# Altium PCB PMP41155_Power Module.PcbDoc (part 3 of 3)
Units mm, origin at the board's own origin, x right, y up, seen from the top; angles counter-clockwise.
Board outline 40.5 x 74.05 mm, 8 copper layers (Top Layer, Layer 1, Layer 2, Layer 3, Layer 4, Layer 5, Layer 6, Bottom Layer), stack 1.58 mm thick; 130 components, 51 nets, 407 pads, 560 vias.
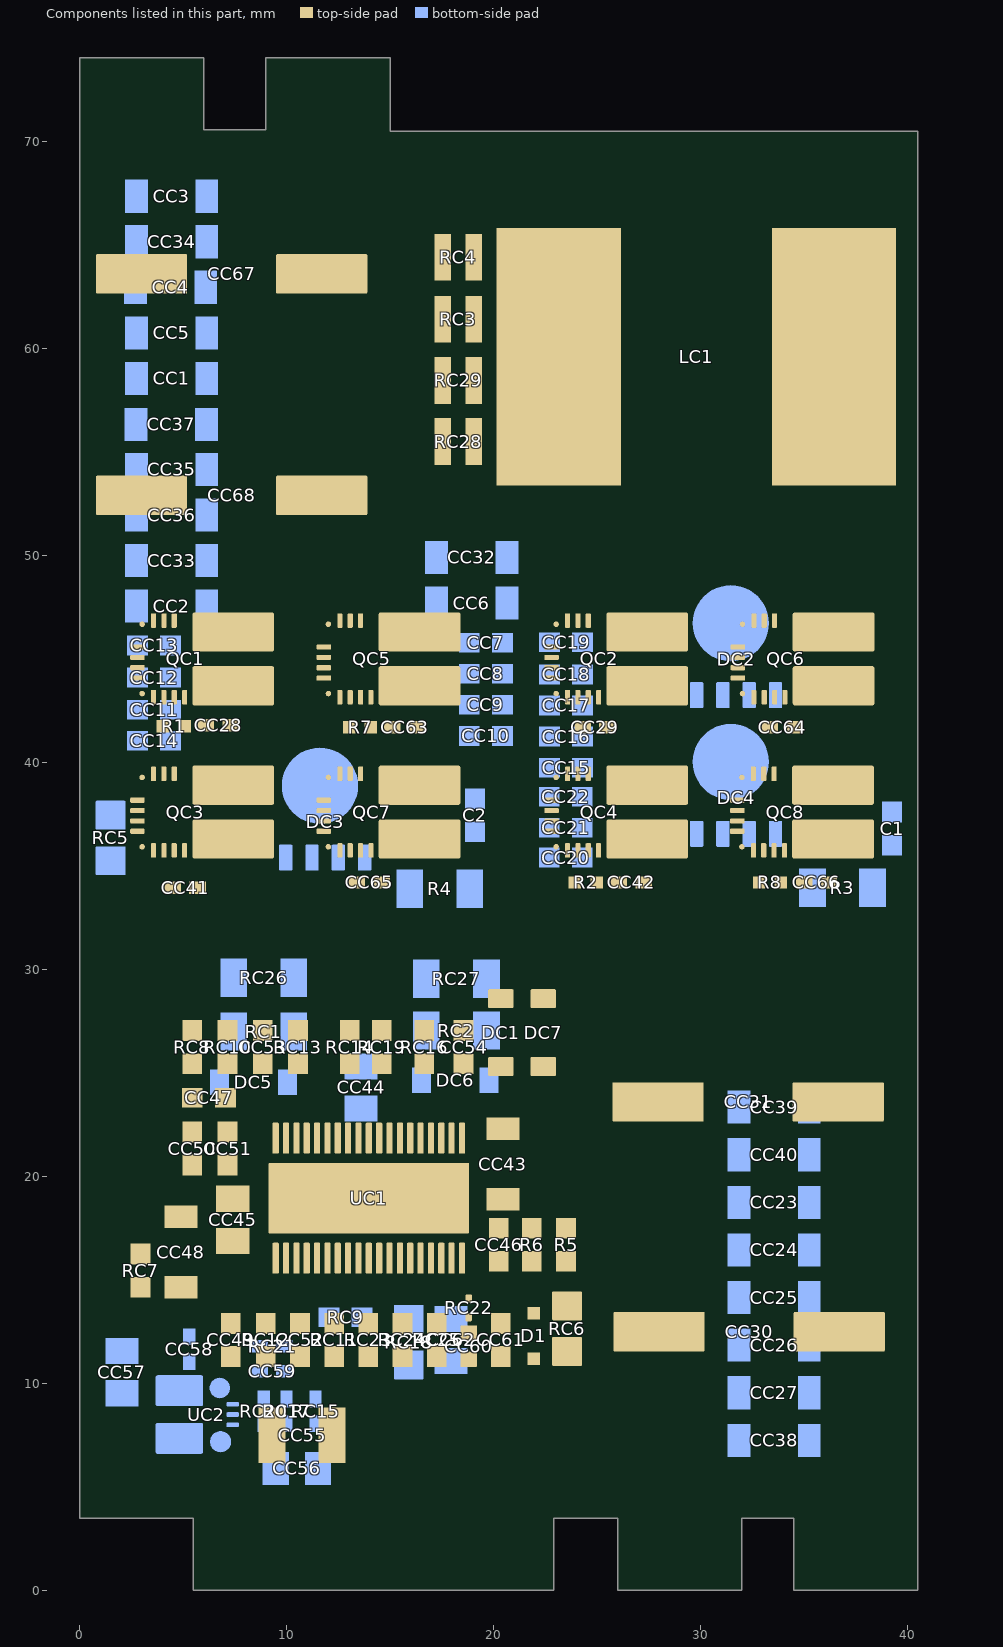
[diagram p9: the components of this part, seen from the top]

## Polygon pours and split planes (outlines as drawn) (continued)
VBUS1 on Bottom Layer "BOTTOM_LAYER_VBUS1_P263" (solid, pour order 263): 31.3,2.6 31.3,3.25 33.8,5.75 33.8,24.05 33,24.85 24.5,24.85 21.9,22.25 21.9,5.75 25.05,2.6
SGND on Bottom Layer "BOTTOM_LAYER_SGND_P221" (solid, remove dead copper, pour order 221): 0.474,5.644 2.624,3.494 19.524,3.494 20.352,4.321 20.352,22.116 19.975,22.494 1.344,22.494 0.474,21.624
SW2 on Bottom Layer "BOTTOM_LAYER_SW2_P250" (solid, pour order 250): 27.45,70 39.55,70 40,69.55 40,43.5 39.3,42.8 20.45,42.8 20,43.25 20,50.45 22.05,52.5 26.45,52.5 26.95,53 26.95,69.5
CSA_DISCH on Bottom Layer "BOTTOM_LAYER_CSA_DISCH_P144" (solid, pour order 144): 5.25,44.85 6,45.6 17.685,45.6 18.189,45.096 18.189,40.711 18.3,40.6 19.65,40.6 19.65,37.5 19.5,37.35 18,37.35 17.45,37.9 5.45,37.9 5.25,38.1
CSB_DISCH on Bottom Layer "BOTTOM_LAYER_CSB_DISCH_P237" (solid, pour order 237): 18.5,69.65 18.85,70 26.05,70 26.55,69.5 26.55,53.5 26.05,53 19,53 18.5,53.5 18.5,69.6
CSA_DISCH on Bottom Layer "BOTTOM_LAYER_CSA_DISCH_P253" (solid, pour order 253): 15.35,69.5 15.85,70 17.85,70 19.2,68.65 19.2,54.3 17.6,52.7 16.1,52.7 15.35,53.45
SGND on Bottom Layer "BOTTOM_LAYER_SGND_P233" (solid, pour order 233): 4.95,37.4 17.7,37.4 17.95,37.15 17.9,37.1 17.9,33.8 16.9,32.8 4.9,32.8 3.45,34.25 3.45,35.9
NetC2_2 on Bottom Layer "BOTTOM_LAYER_NETC2_2_P232" (solid, pour order 232): 19.7,37.175 19.85,37.025 19.85,32.975 19.75,32.875 18.2,32.875 18.05,33.025 18.05,37.075 18.15,37.175
VBUS1 on Bottom Layer "BOTTOM_LAYER_VBUS1_P231" (solid, pour order 231): 24.25,51.1 39.7,51.1 40.05,50.75 40.05,44.5 39.8,44.25 25.4,44.25 24.9,43.75 24.9,35 24.8,34.9 23.8,34.9 23.5,35.2 23.5,50.35
VBAT1 on Bottom Layer "BOTTOM_LAYER_VBAT1_P229" (solid, pour order 229): 19.65,45.05 19.65,41.05 19.35,40.75 18.4,40.75 18.35,40.8 18.35,45.15 19.55,45.15
SGND on Bottom Layer "BOTTOM_LAYER_SGND_P228" (solid, pour order 228): 20.65,51.2 22.6,51.2 23.25,50.55 23.25,34.6 22.1,33.45 21.5,33.45 19.9,35.05 19.9,50.45
VBAT1 on Bottom Layer "BOTTOM_LAYER_VBAT1_P255" (solid, remove dead copper, pour order 255): 5.3,45.1 19.65,45.1 19.65,48.85 14.65,53.85 14.65,70.85 14.5,71 9.45,71 9.3,70.85 9.3,70.5 8.9,70.1 7.15,70.1 3.8,66.75 3.8,40.4 4.05,40.15 4.9,40.15 5.1,40.35 5.1,44.9
SGND on Bottom Layer "BOTTOM_LAYER_SGND_P227" (solid, pour order 227): 3,40.25 3.45,40.7 3.45,66.9 6,69.45 6,72 2.15,72 0.5,70.35 0.5,40.5 0.75,40.25
SW2 on Bottom Layer "BOTTOM_LAYER_SW2_P225" (solid, pour order 225): 25.3,43.45 25.95,44.1 39.75,44.1 40,43.85 40,37 39.85,36.85 38.6,36.85 37.5,37.95 25.5,37.95 25.3,38.15
5V on Bottom Layer "5V" (solid, remove dead copper, pour order 215): 0.585,10.404 0.385,10.204 0.385,8.904 0.585,8.704 5.789,8.704 5.985,8.9 5.985,11.172 5.652,11.504 4.841,11.504 4.626,11.289 4.626,10.895 4.135,10.404
SW2 on Top Layer "TOP_LAYER_SW2_P283" (solid, pour order 283): 27.45,70 39.55,70 40,69.55 40,43.5 39.3,42.8 20.45,42.8 20,43.25 20,50.45 22.05,52.5 26.45,52.5 26.95,53 26.95,69.5
CSB_DISCH on Top Layer "TOP_LAYER_CSB_DISCH_P282" (solid, pour order 282): 18.5,69.65 18.85,70 26.05,70 26.55,69.5 26.55,53.5 26.05,53 19,53 18.5,53.5 18.5,69.6
CSA_DISCH on Top Layer "TOP_LAYER_CSA_DISCH_P281" (solid, pour order 281): 15.35,69.5 15.85,70 17.85,70 18.2,69.65 18.2,53.3 17.6,52.7 16.1,52.7 15.35,53.45
SGND on Top Layer "TOP_LAYER_SGND_P278" (solid, pour order 278): 35.5,1.8 35.65,1.65 39.1,1.65 39.1,3.65 39.9,4.45 39.9,35.8 38.05,37.65 22.752,37.65 22.55,37.41 22.55,30.95 28.25,25.25 33.5,25.25 34.35,24.4 34.35,4.15 34.85,3.65 34.85,1.8 35.45,1.8 35.5,1.85
CSA_DISCH on Top Layer "TOP_LAYER_CSA_DISCH_P276" (solid, pour order 276): 2.444,44.75 18.356,44.75 18.406,44.7 18.406,42.8 18.306,42.7 3.268,42.7 2.444,43.524
SW2 on Top Layer "TOP_LAYER_SW2_P275" (solid, pour order 275): 24.462,39.913 38.512,39.913 38.562,39.863 38.562,37.963 38.462,37.863 24.712,37.863 24.462,38.113
SGND on Top Layer "TOP_LAYER_SGND_P274" (solid, pour order 274): 2.45,37.271 18.417,37.271 18.467,37.221 18.467,35.321 18.367,35.221 3.329,35.221 2.45,36.1
CSA_DISCH on Top Layer "TOP_LAYER_CSA_DISCH_P273" (solid, pour order 273): 4.4,39.85 18.45,39.85 18.5,39.8 18.5,37.9 18.4,37.8 4.65,37.8 4.4,38.05
5V on Top Layer "5V" (solid, remove dead copper, pour order 271): 3.9,10.25 3.9,9.1 4.15,8.85 5.45,8.85 5.7,9.1 5.7,10.2 5.4,10.5 4.15,10.5
SGND on Top Layer "TOP_LAYER_SGND_P261" (solid, pour order 261): 2.5,3.85 0.55,5.8 0.55,18.75 2.3,20.5 21.3,20.5 22.45,19.35 22.45,6.7 19.6,3.85
VBUS1 on Top Layer "TOP_LAYER_VBUS1_P265" (solid, pour order 265): 18.35,21.1 18.55,20.9 21.45,20.9 23.85,18.5 25.65,18.5 25.65,24.2 25.3,24.2 23.95,22.85 18.55,22.85 18.35,22.65
VBUS1 on Top Layer "TOP_LAYER_VBUS1_P222" (solid, pour order 222): 31.3,2.6 31.3,3.25 33.8,5.75 33.8,24.05 33,24.85 25.95,24.85 25.3,24.2 25.3,4.6 27.3,2.6
12V on Top Layer "TOP_LAYER_12V_P042" (solid, pour order 42): 9.5,16.9 9.65,16.75 9.65,15.3 9.2,14.85 7.1,14.85 6.6,15.35 6.6,17.5 8.2,17.5 8.8,16.9
12V on Top Layer "TOP_LAYER_12V_P259" (solid, pour order 259): 9.9,8.85 10.05,8.7 10.05,8.1 10.45,7.7 11.1,7.7 11.3,7.5 11.3,7.2 11.1,7 10.45,7 10,6.55 9.95,6.55 9.95,6.15 6.85,6.15 6.5,6.5 6.5,8.35 7,8.85
SGND on Top Layer "TOP_LAYER_SGND_P254" (solid, pour order 254): 4.65,48.4 6,49.75 6,72 2.15,72 0.5,70.35 0.5,48.65 0.75,48.4
VBAT1 on Top Layer "TOP_LAYER_VBAT1_P236" (solid, remove dead copper, pour order 236): 18.4,45.15 18.4,49.65 14.65,53.4 14.65,70.85 14.5,71 9.45,71 9.3,70.85 9.3,70.5 8.9,70.1 7.15,70.1 4.45,67.4 4.45,45.15
SGND on Top Layer "TOP_LAYER_SGND_P216" (solid, remove dead copper, pour order 216): 2.3,18.95 6.2,15.05 20.1,15.05 22.45,17.4 22.45,19.35 21.136,20.664 2.45,20.664 2.3,20.5
SW2 on Layer 2 "LAYER_2_SW2_P288" (solid, pour order 288): 27.45,70 39.55,70 40,69.55 40,48.7 39.15,47.85 21,47.85 20,48.85 20,50.45 22.05,52.5 26.45,52.5 26.95,53 26.95,69.5
CSB_DISCH on Layer 2 "LAYER_2_CSB_DISCH_P258" (solid, pour order 258): 19.35,69.6 19.75,70 26.05,70 26.55,69.5 26.55,53.5 26.05,53 19.55,53 19.35,53.2
CSA_DISCH on Layer 2 "LAYER_2_CSA_DISCH_P246" (solid, pour order 246): 17.65,70 19.4,68.25 19.4,39.15 17.7,37.45 5.55,37.45 2.95,40.05 2.95,67 5.95,70
VBAT1 on Layer 2 "LAYER_2_VBAT1_P280" (solid, remove dead copper, pour order 280): 14.645,64.35 14.645,70.852 14.495,71.002 9.445,71.002 9.295,70.852 9.295,70.502 8.895,70.102 7.145,70.102 7.145,64.35
5V on Layer 2 "5V" (solid, remove dead copper, pour order 211): 3.9,10.25 3.9,9.1 4.15,8.85 5.45,8.85 5.7,9.1 5.7,10.2 5.4,10.5 4.15,10.5
CSA_DISCH on Layer 2 "LAYER_2_CSA_DISCH_P247" (solid, pour order 247): 15.35,69.5 15.85,70 17.85,70 17.85,52.95 17.6,52.7 16.1,52.7 15.35,53.45
SGND on Layer 2 "LAYER_2_SGND_P226" (solid, pour order 226): 4.65,48.4 6,49.75 6,72 2.15,72 0.5,70.35 0.5,48.65 0.75,48.4
VBUS1 on Layer 2 "LAYER_2_VBUS1_P219" (solid, pour order 219): 25.695,47.6 38.371,47.6 39.883,46.088 39.883,7.838 37.033,4.988 34.083,4.988 31.683,2.588 26.433,2.588 22.45,6.571 22.45,44.355
CSA_DISCH on Layer 1 "LAYER_1_CSA_DISCH_P284" (solid, pour order 284): 17.65,70 19.4,68.25 19.4,39.15 17.7,37.45 5.55,37.45 2.95,40.05 2.95,67 5.95,70
SGND on Layer 1 "LAYER_1_SGND_P223" (solid, pour order 223): 35.5,1.8 35.65,1.65 39.1,1.65 39.1,3.65 39.9,4.45 39.9,35.8 38.05,37.65 25.799,37.65 23.25,35.101 23.25,9.2 26.9,5.55 33.6,5.55 34.35,4.8 34.35,4.15 34.85,3.65 34.85,1.8 35.45,1.8 35.5,1.85
SW2 on Layer 1 "LAYER_1_SW2_P277" (solid, pour order 277): 15.95,25.2 17.45,23.7 20.25,23.7 22.7,26.15 22.7,35.5 24.75,37.55 24.75,37.85 23.4,39.2 19.65,39.2 19.65,32.85 15.95,29.15
VBAT1 on Layer 1 "LAYER_1_VBAT1_P251" (solid, remove dead copper, pour order 251): 14.645,64.35 14.645,70.852 14.495,71.002 9.445,71.002 9.295,70.852 9.295,70.502 8.895,70.102 7.145,70.102 7.145,64.35
CSA_DISCH on Layer 1 "LAYER_1_CSA_DISCH_P238" (solid, pour order 238): 11.3,37.85 11.3,26.1 9.3,24.1 7,24.1 4.35,26.75 4.35,29.45 9.6,34.7 9.6,37.85
SGND on Layer 1 "LAYER_1_SGND_P269" (solid, pour order 269): 18.55,37.25 18.55,35.15 17.05,33.65 3.35,33.65 2.65,34.35 2.65,36.7 3.2,37.25
12V on Layer 1 "LAYER_1_12V_P268" (solid, pour order 268): 7.25,16.05 8.25,16.05 8.75,15.55 8.75,6.45 8.25,5.95 7.45,5.95 6.75,6.65 6.75,15.55
SGND on Layer 1 "LAYER_1_SGND_P248" (solid, pour order 248): 4.65,48.4 6,49.75 6,72 2.15,72 0.5,70.35 0.5,48.65 0.75,48.4
SW2 on Layer 1 "LAYER_1_SW2_P245" (solid, pour order 245): 27.45,70 39.55,70 40,69.55 40,38.55 38.95,37.5 20.8,37.5 19.65,38.65 19.65,50.1 22.05,52.5 26.45,52.5 26.95,53 26.95,69.5
CSB_DISCH on Layer 1 "LAYER_1_CSB_DISCH_P260" (solid, pour order 260): 18.5,69.65 18.85,70 26.05,70 26.55,69.5 26.55,53.5 26.05,53 19,53 18.5,53.5 18.5,69.6

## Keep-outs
Keep-Out Layer:
  text ".Layer_Name" at 14.656,-21.806 h1.52

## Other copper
Top Layer:
  rectangle net COMP_DIR: 16.1,0.25 17.1,4.25
  region net VBUS1: 32,4 26,4 26,0 32,0
  region net SGND: 40.5,4 34.5,4 34.5,0 40.5,0
  rectangle net VBAT1: 9,70.05 15,74.05
  rectangle net SGND: 0,70.05 6,74.05
  rectangle net VFB: 20.9,0.25 21.9,4.25
  rectangle net FB_DIR: 18.5,0.25 19.5,4.25
  rectangle net MODE: 13.7,0.25 14.7,4.25
  rectangle net SGND: 11.3,0.25 12.3,4.25
  rectangle: 8.9,0.25 9.9,4.25
  rectangle net UC_En_Disable: 6.5,0.25 7.5,4.25
  pour cut-out: 17.75,60.2 17.85,60.3 18.7,60.3 18.85,60.15 18.85,59.75 18.7,59.6 17.85,59.6 17.75,59.7
  text ".Layer_Name" at 14.656,-21.806 h1.52
Layer 6:
  region net VBUS1: 32,3.5 26,3.5 26,0 32,0
  region net SGND: 40.5,3.5 34.5,3.5 34.5,0 40.5,0
  rectangle net VBAT1: 9,70.55 15,74.05
  rectangle net SGND: 0,70.55 6,74.05
  pour cut-out: 17.45,39.45 17.25,39.25 17.25,38.95 17.45,38.75 17.8,38.75 17.95,38.9 17.95,39.25 17.75,39.45
Layer 5:
  region net VBUS1: 32,3.5 26,3.5 26,0 32,0
  region net SGND: 40.5,3.5 34.5,3.5 34.5,0 40.5,0
  rectangle net VBAT1: 9,70.55 15,74.05
  rectangle net SGND: 0,70.55 6,74.05
  pour cut-out: 17.45,60.05 17.7,60.3 18.9,60.3 19.1,60.1 19.1,59.75 18.95,59.6 17.65,59.6 17.45,59.8
Layer 3:
  region net VBUS1: 32,3.5 26,3.5 26,0 32,0
  region net SGND: 40.5,3.5 34.5,3.5 34.5,0 40.5,0
  rectangle net VBAT1: 9,70.55 15,74.05
  rectangle net SGND: 0,70.55 6,74.05
  pour cut-out: 5.284,27.684 5.116,27.853 5.116,28.266 5.284,28.434 5.634,28.434 5.784,28.284 5.784,27.834 5.634,27.684
  pour cut-out: 17.5,60.1 17.7,60.3 18.9,60.3 19.1,60.1 19.1,59.75 18.95,59.6 17.65,59.6 17.5,59.75
Layer 4:
  region net VBUS1: 32,3.5 26,3.5 26,0 32,0
  region net SGND: 40.5,3.5 34.5,3.5 34.5,0 40.5,0
  rectangle net VBAT1: 9,70.55 15,74.05
  rectangle net SGND: 0,70.55 6,74.05
  pour cut-out: 17.5,60.1 17.7,60.3 18.9,60.3 19.1,60.1 19.1,59.75 18.95,59.6 17.65,59.6 17.5,59.75
  pour cut-out: 5.4,26.4 5.05,26.4 4.85,26.2 4.85,25.9 5.05,25.7 5.4,25.7 5.55,25.85 5.55,26.25
Layer 1:
  region net VBUS1: 32,3.5 26,3.5 26,0 32,0
  region net SGND: 40.5,3.5 34.5,3.5 34.5,0 40.5,0
  rectangle net VBAT1: 9,70.55 15,74.05
  rectangle net SGND: 0,70.55 6,74.05
  pour cut-out: 17.5,60.1 17.7,60.3 18.9,60.3 19.1,60.1 19.1,59.75 18.95,59.6 17.65,59.6 17.5,59.75
  pour cut-out: 5.284,27.684 5.116,27.853 5.116,28.266 5.284,28.434 5.634,28.434 5.784,28.284 5.784,27.834 5.634,27.684
Layer 2:
  region net VBUS1: 32,3.5 26,3.5 26,0 32,0
  region net SGND: 40.5,3.5 34.5,3.5 34.5,0 40.5,0
  rectangle net VBAT1: 9,70.55 15,74.05
  rectangle net SGND: 0,70.55 6,74.05
  pour cut-out: 18,59.6 18,52.75 10.1,44.85 10.1,37.25 10,37.15 9.6,37.55 9.6,44.85 17.65,52.9 17.65,59.55 17.7,59.6 17.95,59.6
  pour cut-out: 17.5,60.1 17.7,60.3 18.9,60.3 19.1,60.1 19.1,59.75 18.95,59.6 17.65,59.6 17.5,59.75
Bottom Layer:
  region net VBUS1: 32,4 26,4 26,0 32,0
  region net SGND: 40.5,4 34.5,4 34.5,0 40.5,0
  rectangle net SGND: 0,70.05 6,74.05
  rectangle net VBAT1: 9,70.05 15,74.05
  rectangle net COMP: 20.9,0.25 21.9,4.25
  rectangle net 12V: 8.9,0.25 9.9,4.25
  rectangle net DISCH_SS: 18.5,0.25 19.5,4.25
  rectangle: 16.1,0.25 17.1,4.25
  rectangle net PWMH_SYNC: 13.7,0.25 14.7,4.25
  rectangle net SGND: 11.3,0.25 12.3,4.25
  rectangle net 5V: 6.5,0.25 7.5,4.25
  pour cut-out: 17.5,60.1 17.7,60.3 18.9,60.3 19.1,60.1 19.1,59.75 18.95,59.6 17.65,59.6 17.5,59.75
  text ".Layer_Name" at 14.656,-21.806 h1.52

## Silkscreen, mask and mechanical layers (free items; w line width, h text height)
Top Overlay:
  text "PMP41155_Power Module" at 5.5,30.85 h2.75
  text ".Layer_Name" at 14.656,-21.806 h1.52
Bottom Overlay:
  text ".Layer_Name" at 14.656,-21.806 h1.52
Top Paste:
  text ".Layer_Name" at 14.656,-21.806 h1.52
Bottom Paste:
  text ".Layer_Name" at 14.656,-21.806 h1.52
Top Solder:
  region: 32,4 26,4 26,0 32,0
  region: 40.5,4 34.5,4 34.5,0 40.5,0
  rectangle: 0,70.05 6,74.05
  rectangle: 9,70.05 15,74.05
  rectangle: 20.789,0.036 22.039,4.25
  rectangle: 18.389,0.036 19.639,4.25
  rectangle: 6.25,0.036 7.75,4.25
  rectangle: 8.75,0 10,4.25
  rectangle: 11,0 12.5,4.25
  rectangle: 13.5,0.036 15,4.25
  rectangle: 16,0.036 17.25,4.25
  text ".Layer_Name" at 14.656,-21.806 h1.52
  text ".Layer_Name" at 14.656,-21.806 h1.52
Bottom Solder:
  rectangle: 7.127,47.389 14.5,64.5
  region: 32,4 26,4 26,0 32,0
  region: 40.5,4 34.5,4 34.5,0 40.5,0
  rectangle: 0,70.05 6,74.05
  rectangle: 9,70.05 15,74.05
  region: 39.55,58.35 39.55,65.7 27.25,65.7 27.25,58.35
  rectangle: 20.8,0.009 22.05,4.259
  rectangle: 18.381,0 19.631,4.25
  rectangle: 16,0 17.25,4.25
  rectangle: 13.5,0 14.75,4.25
  rectangle: 11,0 12.5,4.25
  rectangle: 8.75,0 10,4.25
  rectangle: 6.25,0 7.75,4.25
  region: 39.6,26.35 39.6,31.717 29.8,31.717 29.8,26.35
  rectangle: 24.35,4.2 30.397,24.647
  region: 14.25,42.45 14.25,45.2 9.35,45.2 9.35,42.45
  rectangle: 20.827,53.6 26.35,65.661
  text ".Layer_Name" at 14.656,-21.806 h1.52
Drill Guide:
  text ".Layer_Name" at 14.656,-21.806 h1.52
M1 Board Outline:
  lines w0.254: 40.5,0 34.5,0 34.5,3.5 32,3.5 32,0 26,0 26,3.5 22.9,3.5 22.9,0 5.5,0 5.5,3.5 0,3.5 0,74 6,74 6,70.5 9,70.5 9,74 15,74 15,70.5 40.5,70.5 40.5,3.5 40.5,0.036
  text ".Layer_Name" at 14.656,-21.806 h1.52
M2 Board Dimensions:
  rectangle: 0,-6.985 3.175,-3.81
  rectangle: 3.175,-10.16 12.7,-6.985
  lines w0.178: 0,-6.985 25.4,-6.985 ; 3.175,-10.16 3.175,-3.81 ; 6.35,-10.16 6.35,-3.81 ; 12.7,-10.16 12.7,-3.81 ; 19.05,-10.16 19.05,-3.81 ; 0,-10.16 25.4,-10.16 25.4,-3.81 0,-3.81 0,-10.16
  text ".Layer_Name" at 14.656,-21.806 h1.52
M3 3D STEP Top:
  text ".Layer_Name" at 14.656,-21.806 h1.52
M4 3D STEP Bottom:
  text ".Layer_Name" at 14.656,-21.806 h1.52
M5 Assembly Top:
  lines w0.254: -7.417,-23.626 160.223,-23.626 ; -7.417,-18.462 160.274,-18.462 ; -7.417,-13.297 -7.417,-28.791 94.31,-28.791 160.274,-28.791 160.274,-13.297 -7.404,-13.297 -7.404,-28.791 32.614,-28.791 ; 55.194,-28.791 55.194,-13.297 ; 87.376,-18.462 87.376,-13.297 ; 108.712,-18.462 108.712,-13.297 ; 124.511,-28.956 124.511,-23.804
  text "COMPONENTS MARKED 'DNP' SHOULD NOT BE POPULATED." at 29.299,-8.09 h1.52
  text "ASSEMBLY VARIANT:" at 29.286,-11.024 h1.52
  text ".VariantName" at 55.601,-11.024 h1.52
  text "PCB VIEWED FROM TOP SIDE" at -5.804,-16.654 h1.52
  text "BOARD #:" at 57.099,-16.654 h1.52
  text ".PRJ_Number" at 70.955,-16.654 h1.52
  text "REV:" at 92.405,-16.654 h1.52
  text ".PCB_Rev" at 99.809,-16.654 h1.52
  text "SVN REV:" at 113.69,-16.654 h1.52
  text ".VersionControl_RevNumber" at 126.543,-16.654 h1.52
  text "TID #:" at 57.099,-21.819 h1.52
  text ".TID" at 70.955,-21.819 h1.52
  text "PLOT NAME =" at -5.804,-27.034 h1.52
  text ".plot_File_Name" at 14.656,-27.034 h1.52
  text "GENERATED    :" at 57.15,-27.034 h1.52
  text ".Print_Date" at 79.235,-27.034 h1.52
  text ".Print_Time" at 97.752,-27.034 h1.52
  text "TEXAS INSTRUMENTS" at 129.87,-27.034 h1.52
M6 Assembly Bottom:
  lines w0.254: -7.429,-18.474 160.261,-18.474 ; -7.379,-23.639 160.261,-23.639 ; 28.334,-28.969 28.334,-23.817 ; 44.133,-18.474 44.133,-13.31 ; 65.468,-18.474 65.468,-13.31 ; 97.65,-28.804 97.65,-13.31 ; 120.231,-28.804 160.249,-28.804 160.249,-13.31 -7.429,-13.31 -7.429,-28.804 58.534,-28.804 160.261,-28.804 160.261,-13.31
  text "COMPONENTS MARKED 'DNP' SHOULD NOT BE POPULATED." at 154.991,-8.077 h1.52
  text ".VariantName" at 128.473,-11.024 h1.52
  text "ASSEMBLY VARIANT:" at 154.864,-11.024 h1.52
  text ".VersionControl_RevNumber" at 26.302,-16.667 h1.52
  text "SVN REV:" at 39.154,-16.667 h1.52
  text ".PCB_Rev" at 53.035,-16.667 h1.52
  text "REV:" at 60.439,-16.667 h1.52
  text ".PRJ_Number" at 81.89,-16.667 h1.52
  text "BOARD #:" at 95.745,-16.667 h1.52
  text "PCB VIEWED FROM BOTTOM SIDE" at 158.648,-16.667 h1.52
  text ".TID" at 81.89,-21.831 h1.52
  text "TID #:" at 95.745,-21.831 h1.52
  text "TEXAS INSTRUMENTS" at 22.974,-27.047 h1.52
  text ".Print_Time" at 55.093,-27.047 h1.52
  text ".Print_Date" at 73.609,-27.047 h1.52
  text "GENERATED    :" at 95.694,-27.047 h1.52
  text ".plot_File_Name" at 138.189,-27.047 h1.52
  text "PLOT NAME =" at 158.648,-27.047 h1.52
M9 Title Sheet:
  drawing of 57 lines, arcs and shapes, not listed
  text "1" at 18.792,204.127 h1.78
  text "2" at 82.182,204.127 h1.78
  text "3" at 145.411,204.127 h1.78
  text "4" at 209.08,204.127 h1.78
  text "5" at 272.555,204.127 h1.78
  text "6" at 336.182,204.127 h1.78
  text "A" at -10.579,175.095 h1.78
  text "A" at 365.341,175.095 h1.78
  text "B" at -10.579,114.643 h1.78
  text "B" at 365.341,114.643 h1.78
  text "C" at -10.579,54.318 h1.78
  text "C" at 365.341,54.318 h1.78
  text "PROJECT TITLE:" at 288.125,7.048 h1.14
  text ".PRJ_Title" at 289.395,3.662 h1.78
  text "DESIGNED FOR:" at 288.125,-0.597 h1.14
  text ".PRJ_Customer" at 289.395,-4.153 h1.78
  text "D" at -10.579,-5.88 h1.78
  text "D" at 365.341,-5.88 h1.78
  text "FILE NAME:" at 288.125,-8.217 h1.14
  text ".PCB_File_Name_No_Path" at 289.395,-11.265 h1.78
  text "Texas Instruments (TI) and/or its licensors do not warrant the accuracy or completeness of this specification" at 161.9,-15.376 h1.14
  text "ENGINEER:" at 288.125,-15.583 h1.14
  text "LAYOUT BY:" at 326.352,-15.583 h1.14
  text "or any information contained therein. TI and/or its licensors do not warrant that this design will meet" at 160.757,-18.237 h1.14
  text ".PRJ_Engineer" at 289.395,-19.52 h1.78
  text ".PCB_Layout" at 327.635,-19.52 h1.78
  text "the specifications, will be suitable for your application or fit for any particular purpose, or will operate in" at 160.757,-21.099 h1.14
  text ".Layer_Name" at 14.656,-21.806 h1.52
  text "ALTIUM DESIGNER VERSION:" at 326.352,-23.457 h1.14
  text "an implementation. TI and/or its licensors do not warrant that the design is production worthy. You should" at 160.757,-23.961 h1.14
  text "completely validate and test your design implementation to confirm the system functionality for your application." at 161.9,-26.822 h1.14
  text ".print_Scale" at 289.395,-26.843 h1.78
  text ".Application_BuildNumber" at 327.635,-26.843 h1.78
  text "1" at 18.792,-32.093 h1.78
  text "2" at 82.182,-32.093 h1.78
  text "3" at 145.411,-32.093 h1.78
  text "4" at 209.08,-32.093 h1.78
  text "5" at 272.555,-32.093 h1.78
  text "6" at 336.182,-32.093 h1.78
M10 Fab Notes:
  drawing of 189 lines, arcs and shapes, not listed
  text "DESIGN INFORMATION" at 314.503,161.447 h1.52
  text "MIN. TRACK WIDTH:" at 298.131,158.091 h1.52
  text "8" at 325.976,158.091 h1.52
  text "MIL" at 329.907,158.091 h1.52
  text "MIN. CLEARANCE:" at 298.131,154.938 h1.52
  text "0.2" at 324.452,154.938 h1.52
  text "mm" at 329.907,154.938 h1.52
  text "MIN. VIA PAD SIZE:" at 298.131,151.785 h1.52
  text "24" at 325.214,151.785 h1.52
  text "MIL" at 329.907,151.785 h1.52
  text "0.05mm (2MIL)" at 315.784,148.486 h1.52
  text "MINIMUM ANNULAR RING" at 289.769,148.277 h1.52
  text "EXTERNAL" at 333.768,148.277 h1.52
  text "PER" at 294.849,145.48 h1.52
  text "IPC-D-275 CLASS 2 LEVEL C" at 300.437,145.48 h1.52
  text "MIL, HOLES" at 338.238,142.928 h1.52
  text "+/-" at 328.27,142.709 h1.52
  text "+/-" at 349.961,142.709 h1.52
  text "REGISTRATION TOLERANCES:" at 289.769,142.682 h1.52
  text "METAL" at 320.243,142.682 h1.52
  text "5" at 334.879,142.683 h1.52
  text "3" at 356.037,142.683 h1.52
  text "MIL" at 358.99,142.682 h1.52
  text "HOLE SIZE TOLERANCE (UNLESS OTHERWISE SPECIFIED):" at 289.769,140.185 h1.52
  text "+/-" at 349.961,140.112 h1.52
  text "3" at 356.037,140.085 h1.52
  text "MIL" at 358.99,140.085 h1.52
  text "MATERIAL:" at 287.87,136.589 h1.52
  text "FR-4 High Tg" at 312.926,133.324 h1.52
  text "X" at 309.257,133.122 h1.52
  text "FR-408" at 298.563,133.007 h1.52
  text "OTHER" at 336.358,133.007 h1.52
  text "62 MIL (1.6mm) +/-10%" at 306.694,129.374 h1.52
  text "X" at 303.643,129.312 h1.52
  text "THICKNESS:" at 289.769,129.165 h1.52
  text "OTHER" at 339.33,129.165 h1.52
  text "TOLERANCE:" at 289.769,125.652 h1.52
  text "X" at 311.314,125.652 h1.52
  text "ANSI IPC-6012 TYPE 3 CLASS 2" at 315.836,125.652 h1.52
  text "OTHER +/-" at 315.835,121.989 h1.52
  text "BOW & TWIST:" at 289.769,118.302 h1.52
  text "X" at 311.314,118.302 h1.52
  text "ANSI IPC-6012 TYPE 3 CLASS 2" at 315.836,118.302 h1.52
  text "OTHER +/-" at 315.835,114.576 h1.52
  text "DRILLING:" at 287.87,111.258 h1.52
  text "NC_DRILL FILES" at 332.599,108.586 h1.52
  text "REFERENCE:" at 289.769,108.486 h1.52
  text "X" at 306.463,108.484 h1.52
  text "AS SHOWN" at 310.984,108.486 h1.52
  text "X" at 329.348,108.486 h1.52
  text "OTHER" at 340.168,104.873 h1.52
  text "PTH COPPER THICKNESS:" at 289.761,104.783 h1.52
  text "X" at 318.697,104.783 h1.52
  text "20-30 um" at 321.948,104.783 h1.52
  text "BOARD FINISH:" at 287.87,101.034 h1.52
  text "SILKSCREEN:" at 291.812,98.237 h1.52
  text "X" at 316.14,98.237 h1.52
  text "TOP" at 319.112,98.237 h1.52
  text "X" at 329.094,98.237 h1.52
  text "BOTTOM" at 332.091,98.237 h1.52
  text "SILKSCREEN COLOR:" at 291.812,94.295 h1.52
  text "X" at 316.115,94.295 h1.52
  text "WHITE" at 319.112,94.295 h1.52
  text "OTHER" at 332.091,94.295 h1.52
  text "X" at 319.442,90.652 h1.52
  text "GREEN" at 322.439,90.652 h1.52
  text "OTHER" at 338.136,90.652 h1.52
  text "SOLDER RESIST COLOR:" at 291.812,90.477 h1.52
  text "X" at 319.442,86.734 h1.52
  text "MATTE" at 322.439,86.734 h1.52
  text "SEMI-GLOSS" at 338.125,86.717 h1.52
  text "IMMERSION GOLD (ENIG)" at 314.819,82.345 h1.52
  text "ENEPIG" at 348.793,82.162 h1.52
  text "SURFACE FINISH:" at 287.87,82.136 h1.52
  text "X" at 310.298,82.136 h1.52
  text "IMM. TIN/SILVER OR EQUIV" at 296.24,78.649 h1.52
  text "OTHER" at 332.599,78.549 h1.52
  text "ARRAY/PANEL:" at 287.87,74.602 h1.52
  text "CUT AND TRIM PER M1 BOARD OUTLINE" at 314.819,74.393 h1.52
  text "N.C. ROUTE" at 314.819,70.94 h1.52
  text "X" at 332.295,70.94 h1.52
  text "V. SCORE" at 336.816,70.94 h1.52
  text "CERTIFICATION:" at 287.87,67.66 h1.52
  text "MATERIALS AND WORKMANSHIP FOR ALL PCBS" at 306.285,67.66 h1.52
  text "TO MEET OR EXCEED THE REQUIREMENTS OF:" at 306.285,65.271 h1.52
  text "X" at 297.078,62.003 h1.52
  text "ANSI IPC-A-600F CLASS ->" at 300.329,62.003 h1.52
  text "X" at 342.188,62.003 h1.52
  text "2" at 344.982,62.003 h1.52
  text "1" at 336.981,61.965 h1.52
  text "3" at 353.973,61.965 h1.52
  text "X" at 317.702,58.252 h1.52
  text "RoHS" at 320.953,58.252 h1.52
  text "OTHER" at 337.321,58.252 h1.52
  text "PER ORDER" at 347.407,58.252 h1.52
  text "ALL BOARDS MUST MEET OR EXCEED UL94-V0 REQUIREMENTS." at 288.569,54.345 h1.52
  text "PCB MUST BEAR THE UL94V-0 UL REGISTERED MATERIAL ID NUMBER" at 288.569,51.397 h1.52
  text "ADDITIONAL REQUIREMENTS:" at 287.87,47.094 h1.52
  text "MICROSECTION:" at 289.769,44.373 h1.52
  text "YES" at 312.775,44.373 h1.52
  text "REQUIRED" at 334.657,40.707 h1.52
  text "BARE BOARD ELEC. TEST:" at 289.769,40.634 h1.52
  text "NONE" at 322.935,40.634 h1.52
  text "X" at 331.66,40.634 h1.52
  text "PER ORDER" at 349.693,40.634 h1.52
  text "XX MIL VIAS REQUIRE NON-CONDUCTIVE FILL AND PLANARIZE" at 294.04,35.428 h1.5
  text "XX MIL VIAS REQUIRE CONDUCTIVE FILL AND PLANARIZE" at 294.243,32.787 h1.52
  text "OUTER XX MIL TRACES REQUIRE 50 OHM SINGLE-ENDED IMPEDANCE" at 294.218,28.637 h1.47
  text "LAYER 2 & 3 (INNER LAYERS) XX MIL WIDE, XX MIL SPACE / TRACES REQUIRE 100 OHM DIFFERENTIAL IMPEDANCE" at 294.015,22.65 h1.52
  text ".Layer_Name" at 14.656,-21.806 h1.52
M11 Gerber Information:
  lines w0.254: -7.417,-23.626 160.223,-23.626 ; -7.417,-18.462 160.274,-18.462 ; -7.417,-13.297 -7.417,-28.791 94.31,-28.791 160.274,-28.791 160.274,-13.297 -7.404,-13.297 -7.404,-28.791 32.614,-28.791 ; 55.194,-28.791 55.194,-13.297 ; 87.376,-18.462 87.376,-13.297 ; 108.712,-18.462 108.712,-13.297 ; 124.511,-28.956 124.511,-23.804
  text "ALL ARTWORK VIEWED FROM TOP SIDE" at -5.804,-16.654 h1.52
  text "BOARD #:" at 57.099,-16.654 h1.52
  text ".PRJ_Number" at 70.955,-16.654 h1.52
  text "REV:" at 92.405,-16.654 h1.52
  text ".PCB_Rev" at 99.809,-16.654 h1.52
  text "SVN REV:" at 113.69,-16.654 h1.52
  text ".VersionControl_RevNumber" at 126.543,-16.654 h1.52
  text "LAYER NAME =" at -5.804,-21.806 h1.52
  text "TID #:" at 57.099,-21.819 h1.52
  text ".TID" at 70.955,-21.819 h1.52
  text "PLOT NAME =" at -5.804,-27.034 h1.52
  text ".plot_File_Name" at 14.656,-27.034 h1.52
  text "GENERATED    :" at 57.15,-27.034 h1.52
  text ".Print_Date" at 79.235,-27.034 h1.52
  text ".Print_Time" at 97.752,-27.034 h1.52
  text "TEXAS INSTRUMENTS" at 129.87,-27.034 h1.52
M12 Stackup:
  drawing of 503 lines, arcs and shapes, not listed
  text "Layer" at 0.263,161.29 h1.52
  text "Name" at 10.674,161.29 h1.52
  text "Material" at 34.29,161.29 h1.52
  text "Thickness" at 56.128,161.29 h1.52
  text "Constant" at 72.634,161.29 h1.52
  text "Board Layer Stack" at 87.108,161.29 h1.52
  text "Top Overlay" at 10.674,158.242 h1.52
  text "Top Solder" at 10.674,155.194 h1.52
  text "Solder Resist" at 34.29,155.194 h1.52
  text "0.39mil" at 56.128,155.194 h1.52
  text "3.5" at 72.634,155.194 h1.52
  text "1" at 0.263,152.146 h1.52
  text "Top Layer" at 10.674,152.146 h1.52
  text "2.76mil" at 56.128,152.146 h1.52
  text "Dielectric 1" at 10.674,149.098 h1.52
  text "FR-4" at 34.29,149.098 h1.52
  text "10.24mil" at 56.128,149.098 h1.52
  text "4.1" at 72.634,149.098 h1.52
  text "2" at 0.263,146.05 h1.52
  text "Layer 1" at 10.674,146.05 h1.52
  text "2.76mil" at 56.128,146.05 h1.52
  text "Dielectric 2" at 10.674,143.002 h1.52
  text "FR-4" at 34.29,143.002 h1.52
  text "3.94mil" at 56.128,143.002 h1.52
  text "4.1" at 72.634,143.002 h1.52
  text "3" at 0.263,139.954 h1.52
  text "Layer 2" at 10.674,139.954 h1.52
  text "2.76mil" at 56.128,139.954 h1.52
  text "Dielectric 3" at 10.674,136.906 h1.52
  text "FR-4" at 34.29,136.906 h1.52
  text "3.94mil" at 56.128,136.906 h1.52
  text "4.2" at 72.634,136.906 h1.52
  text "4" at 0.263,133.858 h1.52
  text "Layer 3" at 10.674,133.858 h1.52
  text "2.76mil" at 56.128,133.858 h1.52
  text "Dielectric 4" at 10.674,130.81 h1.52
  text "FR-4" at 34.29,130.81 h1.52
  text "3.94mil" at 56.128,130.81 h1.52
  text "4.2" at 72.634,130.81 h1.52
  text "5" at 0.263,127.762 h1.52
  text "Layer 4" at 10.674,127.762 h1.52
  text "2.76mil" at 56.128,127.762 h1.52
  text "Dielectric 5" at 10.674,124.714 h1.52
  text "FR-4" at 34.29,124.714 h1.52
  text "3.94mil" at 56.128,124.714 h1.52
  text "4.2" at 72.634,124.714 h1.52
  text "6" at 0.263,121.666 h1.52
  text "Layer 5" at 10.674,121.666 h1.52
  text "2.76mil" at 56.128,121.666 h1.52
  text "Dielectric6" at 10.674,118.618 h1.52
  text "FR-4" at 34.29,118.618 h1.52
  text "3.94mil" at 56.128,118.618 h1.52
  text "4.6" at 72.634,118.618 h1.52
  text "7" at 0.263,115.57 h1.52
  text "Layer 6" at 10.674,115.57 h1.52
  text "2.76mil" at 56.128,115.57 h1.52
  text "Dielectric 7" at 10.674,112.522 h1.52
  text "FR-4" at 34.29,112.522 h1.52
  text "10.24mil" at 56.128,112.522 h1.52
  text "4.2" at 72.634,112.522 h1.52
  text "8" at 0.263,109.474 h1.52
  text "Bottom Layer" at 10.674,109.474 h1.52
  text "2.76mil" at 56.128,109.474 h1.52
  text "Bottom Solder" at 10.674,106.426 h1.52
  text "Solder Resist" at 34.29,106.426 h1.52
  text "0.39mil" at 56.128,106.426 h1.52
  text "3.5" at 72.634,106.426 h1.52
  text "Bottom Overlay" at 10.674,103.378 h1.52
  text ".Layer_Name" at 14.656,-21.806 h1.52
M13 Component Bodies Top:
  text ".Layer_Name" at 14.656,-21.806 h1.52
M14 Component Bodies Bottom:
  text ".Layer_Name" at 14.656,-21.806 h1.52
M15 Courtyards Top:
  text ".Layer_Name" at 14.656,-21.806 h1.52
M16 Courtyards Bottom:
  text ".Layer_Name" at 14.656,-21.806 h1.52
Drill Drawing:
  circle w0.254: c0.778,140.356 r0.847
  lines w0.254: -0.069,137.393 1.625,137.393 0.778,135.7 -0.069,137.393 ; -0.069,143.32 1.625,143.32 1.625,145.013 -0.069,145.013 -0.069,143.32 ; -0.069,147.553 0.355,147.553 0.778,147.13 1.201,147.553 1.625,147.553 1.201,147.976 1.625,148.399 1.201,148.399 0.778,148.823 0.355,148.399 -0.069,148.399 0.355,147.976 -0.069,147.553
  lines w0.381: -1.587,134.556 265.902,134.556 ; -1.587,149.796 265.902,149.796 ; 12.405,130.746 12.405,153.606 ; 27.641,130.746 27.641,153.606 ; 55.319,130.746 55.319,153.606 ; 68.168,130.746 68.168,153.606 ; 86.806,130.746 86.806,153.606 ; 124.895,130.746 124.895,153.606 ; 139.877,130.746 139.877,153.606 ; 158.82,130.746 158.82,153.606 ; 175.326,130.746 175.326,153.606 ; 197.012,130.746 197.012,153.606 ; 230.885,130.746 230.885,153.606 ; -1.587,130.746 265.902,130.746 265.902,153.606 -1.587,153.606 -1.587,130.746
  text "Symbol" at 0.699,150.939 h1.83
  text "Count" at 13.548,150.939 h1.83
  text "Hole Size" at 28.784,150.939 h1.83
  text "Plated" at 56.462,150.939 h1.83
  text "Hole Type" at 69.311,150.939 h1.83
  text "Drill Layer Pair" at 87.949,150.939 h1.83
  text "Via/Pad" at 126.038,150.939 h1.83
  text "Pad Shape" at 141.02,150.939 h1.83
  text "Template" at 159.963,150.939 h1.83
  text "Description" at 176.469,150.939 h1.83
  text "Hole Tolerance (+)" at 198.155,150.939 h1.83
  text "Hole Tolerance (-)" at 232.028,150.939 h1.83
  text "1" at 13.548,147.13 h1.52
  text "10.00mil (0.254mm)" at 28.784,147.13 h1.52
  text "PTH" at 56.462,147.13 h1.52
  text "Round" at 69.311,147.13 h1.52
  text "Top Layer - Bottom Layer" at 87.949,147.13 h1.52
  text "Via" at 126.038,147.13 h1.52
  text "Rounded" at 141.02,147.13 h1.52
  text "v51h25" at 159.963,147.13 h1.52
  text "24" at 13.548,143.32 h1.52
  text "31.50mil (0.800mm)" at 28.784,143.32 h1.52
  text "PTH" at 56.462,143.32 h1.52
  text "Round" at 69.311,143.32 h1.52
  text "Top Layer - Bottom Layer" at 87.949,143.32 h1.52
  text "Via" at 126.038,143.32 h1.52
  text "Rounded" at 141.02,143.32 h1.52
  text "v80h80" at 159.963,143.32 h1.52
  text "124" at 13.548,139.51 h1.52
  text "7.87mil (0.200mm)" at 28.784,139.51 h1.52
  text "PTH" at 56.462,139.51 h1.52
  text "Round" at 69.311,139.51 h1.52
  text "Top Layer - Bottom Layer" at 87.949,139.51 h1.52
  text "Via" at 126.038,139.51 h1.52
  text "Rounded" at 141.02,139.51 h1.52
  text "(Mixed)" at 159.963,139.51 h1.52
  text "411" at 13.548,135.7 h1.52
  text "10.00mil (0.254mm)" at 28.784,135.7 h1.52
  text "PTH" at 56.462,135.7 h1.52
  text "Round" at 69.311,135.7 h1.52
  text "Top Layer - Bottom Layer" at 87.949,135.7 h1.52
  text "Via" at 126.038,135.7 h1.52
  text "Rounded" at 141.02,135.7 h1.52
  text "(Mixed)" at 159.963,135.7 h1.52
  text "560 Total" at 13.548,131.889 h1.52
  text ".Layer_Name" at 14.656,-21.806 h1.52
M17 Embedded Cavity:
  text ".Layer_Name" at 14.656,-21.806 h1.52
M18 Embedded Assembly:
  text ".Layer_Name" at 14.656,-21.806 h1.52
M19 Embedded Keepout:
  text ".Layer_Name" at 14.656,-21.806 h1.52

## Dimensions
40.8,3.5 to 42.05,70.5 on M2 Board Dimensions
0,74.2 to 40.5,73.15 on M2 Board Dimensions
0,-10.16 to 25.4,-10.16 on M2 Board Dimensions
